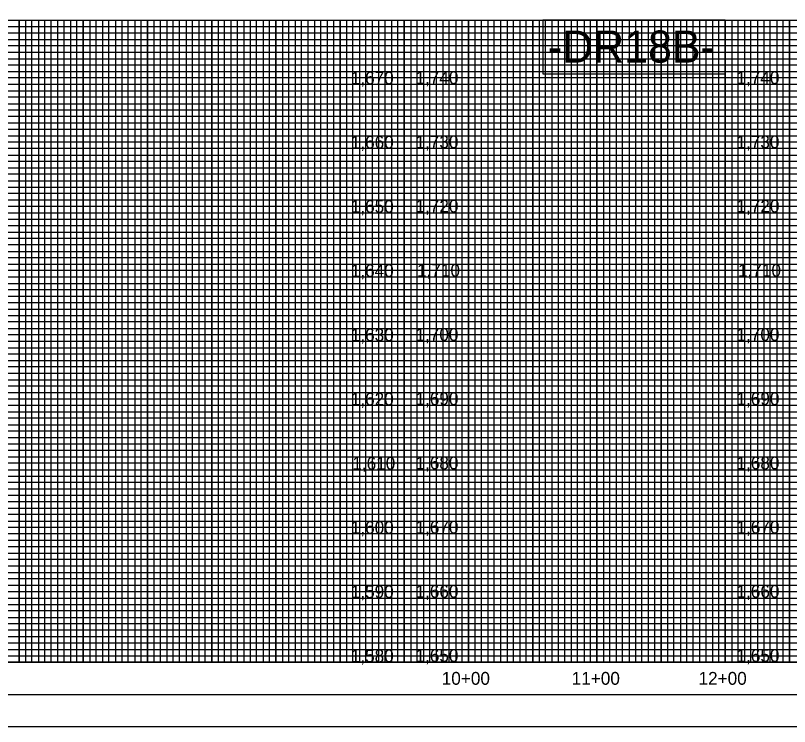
# Model space of a CAD drawing. Extents: x 505602 to 527661, y 418813 to 494436.
# Drawn here: x 506166 to 506769, y 483109 to 483662 of the extents above; entities that cross this region are included whole.
import ezdxf

# ---------------------------------------------------------------- set-up
doc = ezdxf.new("R2010")
doc.units = 0
for name, color, linetype in [('Exist Vertical Profile Vertical Axis Label', 7, 'Continuous'), ('Old_Level_1', 7, 'Continuous'), ('Prop Grid Mask', 7, 'Continuous'), ('Sheet Layout Profile Border Port 1', 7, 'Continuous'), ('Sheet Plot Border Outside CELL', 7, 'Continuous'), ('Sheet Profile CELL', 7, 'Continuous'), ('Sheet Profile Grid Major CELL', 7, 'Continuous'), ('Sheet Profile Grid Middle CELL', 7, 'Continuous'), ('Sheet Profile Grid Minor CELL', 7, 'Continuous')]:
    doc.layers.add(name, color=color, linetype=linetype)

msp = doc.modelspace()

# ---------------------------------------------------------------- linework, layer by layer
at = {"layer": 'Prop Grid Mask'}
msp.add_lwpolyline([(506719.08, 483658.71), (506576.93, 483658.71), (506576.93, 483617), (506719.08, 483617)], close=True, dxfattribs=at)
at = {"layer": 'Sheet Layout Profile Border Port 1'}
for points in [[(506419.08, 483208.71), (506419.08, 483158.71), (506169.08, 483158.71), (506169.08, 483658.71), (506419.08, 483658.71)], [(506469.08, 483658.71), (506769.08, 483658.71), (506769.08, 483158.71), (506469.08, 483158.71)]]:
    msp.add_lwpolyline(points, close=True, dxfattribs=at)
at = {"layer": 'Sheet Plot Border Outside CELL'}
msp.add_lwpolyline([(505602.08, 483108.71), (507286.08, 483108.71), (507286.08, 484208.71), (505602.08, 484208.71)], close=True, dxfattribs=at)
at = {"layer": 'Sheet Profile CELL'}
for p, q in [((505769.08, 483658.71), (507269.08, 483658.71)), ((506469.08, 483158.71), (506469.08, 483658.71)), ((507269.08, 483158.71), (505769.08, 483158.71)), ((505769.08, 483133.71), (507269.08, 483133.71))]:
    msp.add_line(p, q, dxfattribs=at)
msp.add_lwpolyline([(507269.08, 484183.71), (505769.08, 484183.71), (505769.08, 483133.71), (507269.08, 483133.71)], close=True, dxfattribs=at)
at = {"layer": 'Sheet Profile Grid Major CELL'}
for p, q in [((506269.08, 483658.71), (506319.08, 483658.71)), ((506369.08, 483658.71), (506419.08, 483658.71)), ((506469.08, 483658.71), (506519.08, 483658.71)), ((506719.08, 483658.71), (506769.08, 483658.71))]:
    msp.add_line(p, q, dxfattribs=at)
for points in [[(506119.08, 483158.71), (506169.08, 483158.71), (506169.08, 483658.71), (506219.08, 483658.71), (506219.08, 483158.71), (506269.08, 483158.71), (506269.08, 483658.71), (506319.08, 483658.71), (506319.08, 483158.71), (506369.08, 483158.71), (506369.08, 483658.71), (506419.08, 483658.71), (506419.08, 483158.71), (506469.08, 483158.71), (506469.08, 483658.71), (506519.08, 483658.71), (506519.08, 483158.71), (506569.08, 483158.71), (506569.08, 483658.71), (506619.08, 483658.71), (506619.08, 483158.71), (506669.08, 483158.71), (506669.08, 483658.71), (506719.08, 483658.71), (506719.08, 483158.71), (506769.08, 483158.71), (506769.08, 483658.71), (506819.08, 483658.71)], [(506119.08, 483658.71), (506169.08, 483658.71), (506169.08, 483158.71), (506219.08, 483158.71), (506219.08, 483658.71), (506269.08, 483658.71), (506269.08, 483158.71), (506319.08, 483158.71), (506319.08, 483658.71), (506369.08, 483658.71), (506369.08, 483158.71), (506419.08, 483158.71), (506419.08, 483658.71), (506469.08, 483658.71), (506469.08, 483158.71), (506519.08, 483158.71), (506519.08, 483658.71), (506569.08, 483658.71), (506569.08, 483158.71), (506619.08, 483158.71), (506619.08, 483658.71), (506669.08, 483658.71), (506669.08, 483158.71), (506719.08, 483158.71), (506719.08, 483658.71), (506769.08, 483658.71), (506769.08, 483158.71), (506819.08, 483158.71)], [(507269.08, 483608.71), (505769.08, 483608.71)], [(507269.08, 483558.71), (505769.08, 483558.71), (505769.08, 483508.71), (507269.08, 483508.71)], [(507269.08, 483458.71), (505769.08, 483458.71), (505769.08, 483408.71), (507269.08, 483408.71)], [(507269.08, 483358.71), (505769.08, 483358.71), (505769.08, 483308.71), (507269.08, 483308.71)], [(507269.08, 483258.71), (505769.08, 483258.71), (505769.08, 483258.71), (505769.08, 483208.71), (507269.08, 483208.71)], [(507269.08, 483158.71), (505769.08, 483158.71)]]:
    msp.add_lwpolyline(points, dxfattribs=at)
at = {"layer": 'Sheet Profile Grid Middle CELL'}
for points in [[(506144.08, 483158.71), (506194.08, 483158.71), (506194.08, 483658.71), (506244.08, 483658.71), (506244.08, 483158.71), (506294.08, 483158.71), (506294.08, 483658.71), (506344.08, 483658.71), (506344.08, 483158.71), (506394.08, 483158.71), (506394.08, 483158.71), (506394.08, 483658.71), (506444.08, 483658.71), (506444.08, 483158.71), (506494.08, 483158.71), (506494.08, 483658.71), (506544.08, 483658.71), (506544.08, 483158.71), (506594.08, 483158.71), (506594.08, 483658.71), (506644.08, 483658.71), (506644.08, 483158.71), (506694.08, 483158.71), (506694.08, 483658.71), (506744.08, 483658.71), (506744.08, 483158.71), (506794.08, 483158.71)], [(505769.08, 483633.71), (507269.08, 483633.71)], [(507269.08, 483583.71), (505769.08, 483583.71), (505769.08, 483533.71), (507269.08, 483533.71)], [(507269.08, 483483.71), (505769.08, 483483.71), (505769.08, 483433.71), (507269.08, 483433.71)], [(507269.08, 483383.71), (505769.08, 483383.71), (505769.08, 483333.71), (507269.08, 483333.71)], [(507269.08, 483283.71), (505769.08, 483283.71), (505769.08, 483233.71), (507269.08, 483233.71)], [(507269.08, 483183.71), (505769.08, 483183.71)]]:
    msp.add_lwpolyline(points, dxfattribs=at)
at = {"layer": 'Sheet Profile Grid Minor CELL'}
for p, q in [((505819.08, 483653.71), (507219.08, 483653.71)), ((507219.08, 483648.71), (505819.08, 483648.71)), ((505819.08, 483643.71), (507219.08, 483643.71)), ((507219.08, 483638.71), (505819.08, 483638.71)), ((505819.08, 483628.71), (507219.08, 483628.71)), ((507219.08, 483623.71), (505819.08, 483623.71)), ((505819.08, 483618.71), (507219.08, 483618.71)), ((507219.08, 483613.71), (505819.08, 483613.71)), ((505819.08, 483603.71), (507219.08, 483603.71)), ((507219.08, 483598.71), (505819.08, 483598.71)), ((505819.08, 483593.71), (507219.08, 483593.71)), ((507219.08, 483588.71), (505819.08, 483588.71)), ((505819.08, 483578.71), (507219.08, 483578.71)), ((507219.08, 483573.71), (505819.08, 483573.71)), ((505819.08, 483568.71), (507219.08, 483568.71)), ((507219.08, 483563.71), (505819.08, 483563.71)), ((505819.08, 483553.71), (507219.08, 483553.71)), ((507219.08, 483548.71), (505819.08, 483548.71)), ((505819.08, 483543.71), (507219.08, 483543.71)), ((507219.08, 483538.71), (505819.08, 483538.71)), ((505819.08, 483528.71), (507219.08, 483528.71)), ((507219.08, 483523.71), (505819.08, 483523.71)), ((505819.08, 483518.71), (507219.08, 483518.71)), ((507219.08, 483513.71), (505819.08, 483513.71)), ((505819.08, 483503.71), (507219.08, 483503.71)), ((507219.08, 483498.71), (505819.08, 483498.71)), ((505819.08, 483493.71), (507219.08, 483493.71)), ((507219.08, 483488.71), (505819.08, 483488.71)), ((505819.08, 483478.71), (507219.08, 483478.71)), ((507219.08, 483473.71), (505819.08, 483473.71)), ((505819.08, 483468.71), (507219.08, 483468.71)), ((507219.08, 483463.71), (505819.08, 483463.86)), ((505819.08, 483453.71), (507219.08, 483453.71)), ((507219.08, 483448.71), (505819.08, 483448.71)), ((505819.08, 483443.71), (507219.08, 483443.71)), ((507219.08, 483438.71), (505819.08, 483438.71)), ((505819.08, 483428.71), (507219.08, 483428.71)), ((507219.08, 483423.71), (505819.08, 483423.71)), ((505819.08, 483418.71), (507219.08, 483418.71)), ((507219.08, 483413.71), (505819.08, 483413.71)), ((505819.08, 483403.71), (507219.08, 483403.71)), ((507219.08, 483398.71), (505819.08, 483398.71)), ((505819.08, 483393.71), (507219.08, 483393.71)), ((507219.08, 483388.71), (505819.08, 483388.71)), ((505819.08, 483378.71), (507219.08, 483378.71)), ((507219.08, 483373.71), (505819.08, 483373.71)), ((505819.08, 483368.71), (507219.08, 483368.71)), ((507219.08, 483363.71), (505819.08, 483363.71)), ((505819.08, 483353.71), (507219.08, 483353.71)), ((507219.08, 483348.71), (505819.08, 483348.71)), ((505819.08, 483343.71), (507219.08, 483343.71)), ((507219.08, 483338.71), (505819.08, 483338.71)), ((505819.08, 483328.71), (507219.08, 483328.71)), ((507219.08, 483323.71), (505819.08, 483323.71)), ((505819.08, 483318.71), (507219.08, 483318.71)), ((507219.08, 483313.71), (505819.08, 483313.71)), ((505819.08, 483303.71), (507219.08, 483303.71)), ((507219.08, 483298.71), (505819.08, 483298.71)), ((505819.08, 483293.71), (507219.08, 483293.71)), ((507219.08, 483288.71), (505819.08, 483288.71)), ((505819.08, 483278.71), (507219.08, 483278.71)), ((507219.08, 483273.71), (505819.08, 483273.71)), ((505819.08, 483268.71), (507219.08, 483268.71)), ((507219.08, 483263.71), (505819.08, 483263.71)), ((505819.08, 483253.71), (507219.08, 483253.71)), ((507219.08, 483248.71), (505819.08, 483248.71)), ((505819.08, 483243.71), (507219.08, 483243.71)), ((507219.08, 483238.71), (505819.08, 483238.71)), ((505819.08, 483228.71), (507219.08, 483228.71)), ((507219.08, 483223.71), (505819.08, 483223.71)), ((505819.08, 483218.71), (507219.08, 483218.71)), ((507219.08, 483213.71), (505819.08, 483213.71)), ((505819.08, 483203.71), (507219.08, 483203.71)), ((507219.08, 483198.71), (505819.08, 483198.71)), ((505819.08, 483193.71), (507219.08, 483193.71)), ((507219.08, 483188.71), (505819.08, 483188.71)), ((505819.08, 483178.71), (507219.08, 483178.71)), ((507219.08, 483173.71), (505819.08, 483173.71)), ((505819.08, 483168.71), (507219.08, 483168.71)), ((505819.08, 483163.71), (507219.08, 483163.71))]:
    msp.add_line(p, q, dxfattribs=at)
for points in [[(506164.08, 483658.71), (506174.08, 483658.71), (506174.08, 483158.71), (506179.08, 483158.71), (506179.08, 483658.71), (506184.08, 483658.71), (506184.08, 483158.71), (506189.08, 483158.71), (506189.08, 483658.71), (506199.08, 483658.71), (506199.08, 483158.71), (506204.08, 483158.71), (506204.08, 483658.71), (506209.08, 483658.71), (506209.08, 483158.71), (506214.08, 483158.71), (506214.08, 483658.71), (506224.08, 483658.71), (506224.08, 483158.71), (506229.08, 483158.71), (506229.08, 483658.71), (506234.08, 483658.71), (506234.08, 483158.71), (506239.08, 483158.71), (506239.08, 483658.71), (506249.08, 483658.71), (506249.08, 483158.71), (506254.08, 483158.71), (506254.08, 483658.71), (506259.08, 483658.71), (506259.08, 483158.71), (506264.08, 483158.71), (506264.08, 483658.71), (506274.08, 483658.71), (506274.08, 483158.71), (506279.08, 483158.71), (506279.08, 483658.71), (506284.08, 483658.71), (506284.08, 483158.71), (506289.08, 483158.71), (506289.08, 483658.71), (506299.08, 483658.71), (506299.08, 483158.71), (506304.08, 483158.71), (506304.08, 483658.71), (506309.08, 483658.71), (506309.08, 483158.71), (506314.08, 483158.71), (506314.08, 483658.71), (506324.08, 483658.71), (506324.08, 483158.71), (506329.08, 483158.71), (506329.08, 483658.71), (506334.08, 483658.71), (506334.08, 483158.71), (506339.08, 483158.71), (506339.08, 483658.71), (506349.08, 483658.71)], [(506349.08, 483658.71), (506349.08, 483158.71), (506354.08, 483158.71), (506354.08, 483658.71), (506359.08, 483658.71), (506359.08, 483158.71), (506364.08, 483158.71), (506364.08, 483658.71), (506374.08, 483658.71), (506374.08, 483158.71), (506379.08, 483158.71), (506379.08, 483658.71), (506384.08, 483658.71), (506384.08, 483158.71), (506389.08, 483158.71), (506389.08, 483658.71), (506399.08, 483658.71), (506399.08, 483158.71), (506404.08, 483158.71), (506404.08, 483658.71), (506409.08, 483658.71), (506409.08, 483158.71), (506414.08, 483158.71), (506414.08, 483658.71), (506424.08, 483658.71), (506424.08, 483158.71), (506429.08, 483158.71), (506429.08, 483658.71), (506434.08, 483658.71), (506434.08, 483158.71), (506439.08, 483158.71), (506439.08, 483658.71), (506449.08, 483658.71), (506449.08, 483158.71), (506454.08, 483158.71), (506454.08, 483658.71), (506459.08, 483658.71), (506459.08, 483158.71), (506464.08, 483158.71), (506464.08, 483658.71), (506474.08, 483658.71), (506474.08, 483158.71), (506474.08, 483158.71), (506479.08, 483158.71), (506479.08, 483658.71), (506484.08, 483658.71), (506484.08, 483158.71), (506489.08, 483158.71), (506489.08, 483658.71), (506499.08, 483658.71), (506499.08, 483158.71), (506504.08, 483158.71), (506504.08, 483658.71), (506509.08, 483658.71), (506509.08, 483158.71), (506514.08, 483158.71), (506514.08, 483658.71), (506524.08, 483658.71), (506524.08, 483158.71), (506529.08, 483158.71), (506529.08, 483658.71), (506534.08, 483658.71), (506534.08, 483158.71), (506539.08, 483158.71), (506539.08, 483658.71), (506549.08, 483658.71), (506549.08, 483158.71), (506554.08, 483158.71), (506554.08, 483658.71), (506559.08, 483658.71), (506559.08, 483158.71), (506564.08, 483158.71), (506564.08, 483658.71), (506574.08, 483658.71), (506574.08, 483158.71), (506579.08, 483158.71), (506579.08, 483658.71), (506584.08, 483658.71), (506584.08, 483158.71), (506589.08, 483158.71), (506589.08, 483658.71), (506599.08, 483658.71), (506599.08, 483158.71), (506604.08, 483158.71), (506604.08, 483658.71), (506609.08, 483658.71), (506609.08, 483158.71), (506614.08, 483158.71), (506614.08, 483658.71), (506624.08, 483658.71), (506624.08, 483158.71), (506628.78, 483159.26), (506629.08, 483158.71), (506629.08, 483658.71), (506634.08, 483658.71), (506634.08, 483158.71), (506639.08, 483158.71), (506639.08, 483658.71), (506649.08, 483658.71), (506649.08, 483158.71), (506654.08, 483158.71)], [(506654.08, 483158.71), (506654.08, 483658.71), (506659.08, 483658.71), (506659.08, 483158.71), (506664.08, 483158.71), (506664.08, 483658.71), (506674.08, 483658.71), (506674.08, 483158.71), (506679.08, 483158.71), (506679.08, 483658.71), (506684.08, 483658.71), (506684.08, 483158.71), (506689.08, 483158.71), (506689.08, 483658.71), (506699.08, 483658.71), (506699.08, 483158.71), (506704.08, 483158.71), (506704.08, 483658.71), (506709.08, 483658.71), (506709.08, 483158.71), (506714.08, 483158.71), (506714.08, 483658.71), (506724.08, 483658.71), (506724.08, 483158.71), (506729.08, 483158.71), (506729.08, 483658.71), (506734.08, 483658.71), (506734.08, 483158.71), (506739.08, 483158.71), (506739.08, 483658.71), (506749.08, 483658.71), (506749.08, 483158.71), (506754.08, 483158.71), (506754.08, 483658.71), (506759.08, 483658.71), (506759.08, 483158.71), (506764.08, 483158.71), (506764.08, 483658.71), (506774.08, 483658.71)]]:
    msp.add_lwpolyline(points, dxfattribs=at)

# ---------------------------------------------------------------- texts
at = {"layer": 'Exist Vertical Profile Vertical Axis Label'}
for s, p in [('1,670', (506427.38, 483608.71)), ('1,740', (506477.78, 483608.96)), ('1,740', (506727.78, 483608.96)), ('1,660', (506427.38, 483558.71)), ('1,730', (506477.78, 483558.96)), ('1,730', (506727.78, 483558.96)), ('1,650', (506427.38, 483508.71)), ('1,720', (506477.78, 483508.96)), ('1,720', (506727.78, 483508.96)), ('1,640', (506427.38, 483458.71)), ('1,710', (506478.97, 483458.96)), ('1,710', (506728.97, 483458.96)), ('1,630', (506427.38, 483408.71)), ('1,700', (506477.78, 483408.96)), ('1,700', (506727.78, 483408.96)), ('1,620', (506427.38, 483358.71)), ('1,690', (506477.78, 483358.96)), ('1,690', (506727.78, 483358.96)), ('1,610', (506428.57, 483308.71)), ('1,680', (506477.78, 483308.96)), ('1,680', (506727.78, 483308.96)), ('1,600', (506427.38, 483258.71)), ('1,670', (506477.78, 483258.96)), ('1,670', (506727.78, 483258.96)), ('1,590', (506427.38, 483208.71)), ('1,660', (506477.78, 483208.96)), ('1,660', (506727.78, 483208.96)), ('1,580', (506427.38, 483158.71)), ('1,650', (506477.78, 483158.96)), ('1,650', (506727.78, 483158.96)), ('10+00', (506498.21, 483141.21)), ('11+00', (506599.41, 483141.21)), ('12+00', (506698.21, 483141.21))]:
    msp.add_text(s, height=10, dxfattribs=at).set_placement(p)
at = {"layer": 'Old_Level_1'}
msp.add_text('-DR18B-', height=25, dxfattribs=at).set_placement((506580.88, 483625.68))

doc.saveas('drawing.dxf')
